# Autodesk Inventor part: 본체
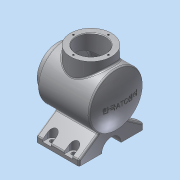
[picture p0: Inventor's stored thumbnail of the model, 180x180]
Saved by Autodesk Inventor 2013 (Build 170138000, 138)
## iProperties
Created: 2017-04
Part Number: 본체
Material: 알루미늄 6061
Document SubType Name: Modeling
Designer: dgall
Density: 2.71 g/cm^3
Mass: 1670.76 g
Surface Area: 1066.85 cm^2
Volume: 616.515 cm^3
Author: dgall
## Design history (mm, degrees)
sketch "스케치1"
  geometry: L1 (-60, 0)-(-60, 38); L2 (-60, 38)-(-48, 38); L3 (-48, 38)-(-48, 50); L4 (-48, 50)-(48.336, 50); L5 (-60, 0)-(60, 0); A1 r 113 centre (-53, 0) between (60, 0) and (48.336, 50); 2 further points
  constraints: 10 end point, 3 parallel, 2 point on circle, 1 centre point, 1 coincident, 1 horizontal alignment, 1 midpoint, 1 perpendicular, 1 vertical
  dimensions: "d0" = 76 diameter of L2 L5; "d2" = 100 diameter of L4 L5; "d3" = 113 radius of A1; "d4" = 12 distance of L1.end L2.end; "d5" = 108 horizontal distance of L5.end L3.end
revolve "회전1" sketch "스케치1" stored, may be unused: angle "d6" = 90 deg
sketch "스케치2"
  geometry: L1 (-48, -38)-(-60, -38) reference; L2 (-60, -38)-(-60, 38) reference; L3 (-60, 38)-(-48, 38) reference; L4 (-48, 38)-(-48, 50) reference; L5 (-48, 50)-(48.336, 50) reference; L6 (48.336, -50)-(-48, -50) reference; L7 (-48, -50)-(-48, -38) reference; L8 (-60, 27)-(-38, 27); L9 (-38, 27)-(-38, 40); L10 (-38, 40)-(41.916, 40); L11 (50, 0)-(-60, 0); A1 r 113 centre (-53, 0) between (48.336, -50) and (48.336, 50) reference; A2 r 103 centre (-53, 0) between (50, 0) and (41.916, 40); 1 further point
  constraints: 8 end point, 2 horizontal alignment, 2 perpendicular, 2 point on circle, 1 centre point, 1 concentric, 1 midpoint, 1 parallel, 1 point on line
  dimensions: "d7" = 10 radial gap between concentric circles of A1 A2; "d8" = 54 diameter of L8 L11; "d9" = 80 diameter of L10 L11; "d10" = 22 distance of L8.start L8.end
revolve "회전2" sketch "스케치2" stored, may be unused: angle "d11" = 90 deg
fillet "모깎기1" dims "d12" = 3
chamfer "모따기1" distance "d13" = 1; stored, may be unused: second distance "d14" = 2, angle "d15" = 45 deg
node "작업 평면1"
sketch "스케치3"
  geometry: L1 (60, 38)-(60, -38) reference; C1 r 38 at (-2, 0); 1 further point
  constraints: 1 centre point, 1 horizontal alignment
  dimensions: "d17" = 38 radius of C1; "d18" = 62 distance from line of L1 C1.centre
extrude "돌출1" join sketch "스케치3" stored distance "d19" = 10; taper "d20" = 0 deg
hole "구멍1" diameter "d23" = 54; stored, may be unused: countersink angle "d27" = 90 deg, drill point angle "d29" = 0 deg; dims "d21" = 10, "d22" = 10, "d24" = 6, "d25" = 4, "d26" = 2, "d28" = 8
sketch "스케치4"
  geometry: C1 r 27 at (0, 0) reference; C2 r 27 at (0, 0) reference; C3 r 38 at (0, 0) reference; 2 further points
  constraints: 1 vertical alignment
  dimensions: "d30" = 32.5 distance of C1.centre point (0, 32.5)
hole "구멍2" sketch "스케치4" at (0, 32.5) diameter "d31" = 3.242; stored, may be unused: countersink angle "d35" = 90 deg, drill point angle "d37" = 120 deg; dims "d32" = 8, "d33" = 4, "d34" = 2, "d36" = 10
sketch "스케치5"
  geometry: C1 r 38 at (0, 0) reference; C2 r 28 at (0, 0) reference; C3 r 38 at (0, 0) reference; 1 further point
  constraints: 1 vertical alignment
  dimensions: "d41" = 32.5 distance of C1.centre point (0, 32.5)
hole "구멍3" sketch "스케치5" at (0, 32.5) diameter "d42" = 3.242; stored, may be unused: countersink angle "d46" = 90 deg, drill point angle "d48" = 120 deg; dims "d43" = 8, "d44" = 4, "d45" = 2, "d47" = 10
sketch "스케치6"
  geometry: L1 (32.558, 37.947)-(65, 37.947) reference; L2 (65, 37.947)-(65, 26.926) reference; L3 (65, 26.926)-(29.58, 26.926) reference; L4 (29.58, -26.926)-(65, -26.926) reference; L5 (65, -26.926)-(65, -37.947) reference; L6 (65, -37.947)-(32.558, -37.947) reference; L7 (-45.101, 21.584)-(-72, 60); L8 (-72, 60)-(-82, 60); L9 (-82, 60)-(-82, -60); L10 (-82, -60)-(-72, -60); L11 (-72, -60)-(-45.101, -21.584); A1 r 50 centre (0, 0) between (32.558, 37.947) and (32.558, -37.947) reference; A2 r 40 centre (0, 0) between (29.58, 26.926) and (29.58, -26.926) reference; A3 r 50 centre (0, 0) between (-45.101, 21.584) and (-45.101, -21.584); 2 further points
  constraints: 10 end point, 4 point on circle, 2 parallel, 2 perpendicular, 1 centre point, 1 concentric, 1 horizontal alignment, 1 midpoint
  dimensions: "d52" = 120 distance of L8.end L9.end; "d54" = 10 distance of L9.end L10.end; "d55" = 55 deg angle of L8 L7; "d56" = 55 deg angle of L10 L11; "d57" = 82 distance from line of A1.centre L9
extrude "돌출2" join sketch "스케치6" stored distance "d58" = 80; taper "d59" = 0 deg
sketch "스케치7"
  geometry: L1 (21.584, -45.101)-(60, -72) reference; L2 (60, -72)-(60, -82) reference; L3 (60, -82)-(-60, -82) reference; L4 (-60, -82)-(-60, -72) reference; L5 (-60, -72)-(-21.584, -45.101) reference; L6 (0, 65)-(0, 50) reference; C1 r 39.998 at (0, 0) reference; C2 r 18 at (0, -82); A1 r 50 centre (0, 0) between (21.584, -45.101) and (0, 50) reference; A2 r 50 centre (0, 0) between (0, 50) and (-21.584, -45.101) reference; A3 r 50 centre (0, 0) between (-21.584, -45.101) and (21.584, -45.101) reference
  constraints: 1 centre point, 1 midpoint
  dimensions: "d60" = 18 radius of C2
extrude "돌출3" cut sketch "스케치7" stored distance "d61" = 80; taper "d62" = 0 deg
node "작업 평면2"
sketch "스케치8"
  geometry: L1 (0, -76.971)-(80, -76.971) reference; L2 (80, -76.971)-(80, -120) reference; L3 (80, -120)-(0, -120) reference; L4 (0, -120)-(0, -76.971) reference; L5 (80, -43.029)-(0, -43.029) reference; L6 (0, -43.029)-(0, 0) reference; L7 (0, 0)-(80, 0) reference; L8 (80, 0)-(80, -43.029) reference; L9 (12, 0)-(12, -10); L10 (28, -10)-(28, 0); A1 r 8 centre (20, -10) between (12, -10) and (28, -10); 1 further point
  constraints: 4 end point, 2 point on circle, 2 point on line, 2 tangent, 1 centre point, 1 parallel, 1 perpendicular
  dimensions: "d64" = 8 radius of A1; "d66" = 20 horizontal distance of A1.centre L6.end; "d67" = 10 distance of L9.start L9.end
extrude "돌출4" cut sketch "스케치8" distance "d68" = 20; taper "d69" = 0 deg
hole "구멍4" diameter "d72" = 8; stored, may be unused: countersink angle "d76" = 90 deg, drill point angle "d78" = 120 deg; dims "d70" = 10, "d71" = 10, "d73" = 8, "d74" = 4, "d75" = 2, "d77" = 10
fillet "모깎기2" dims "d82" = 3
fillet "모깎기3" dims "d83" = 3
node "작업 평면3"
sketch "스케치9"
  geometry: 2 further points
  constraints: 1 coincident, 1 other
feature "엠보싱1" sketch "스케치9" dims "d0" = 76, "d2" = 100, "d3" = 113, "d4" = 12, "d5" = 108, "d85" = 0.5, "d86" = 0
chamfer "모따기2" distance "d87" = 1; stored, may be unused: second distance "d88" = 2, angle "d89" = 45 deg
node "솔리드1"
pattern_circular "원형 패턴1" dims angle "d39" = 360 deg
pattern_circular "원형 패턴2" dims angle "d50" = 360 deg
pattern_linear "직사각형 패턴1"
mirror "대칭1"
node "절단 모서리 투영1"
node "절단 모서리 투영2"
node "절단 모서리 투영3"
node "절단 모서리 투영4"
node "절단 모서리 투영5"
node "절단 모서리 투영6"
other parameters: "d16" = 65, "d63" = -6, "d84" = -108
